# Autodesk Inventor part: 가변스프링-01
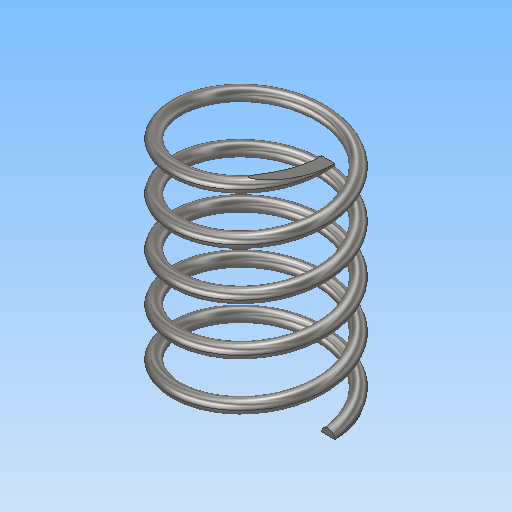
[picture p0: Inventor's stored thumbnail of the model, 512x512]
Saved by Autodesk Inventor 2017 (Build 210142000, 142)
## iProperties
Part Number: 가변스프링-01
Material: 강철, 연강
Document SubType Name: Modeling
Designer: MRC
Density: 7.85 g/cm^3
Appearance: 반연마
Mass: 8.42301 g
Surface Area: 21.7219 cm^2
Volume: 1.07299 cm^3
Author: MRC
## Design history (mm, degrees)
sketch "스케치1"
  geometry: L1 (0, 0)-(11, 0); L2 (11, 0)-(11, 36.411); L3 (11, 36.411)-(0, 36.411); L4 (0, 36.411)-(0, 0); C1 r 1 at (11, 0)
  constraints: 8 end point, 2 parallel, 1 centre point, 1 coincident, 1 horizontal, 1 perpendicular
  dimensions: "d0" = 36.4112 distance of L3.end L1.start (derived); "d1" = 22 diameter of L2 L4; "d2" = 2 diameter of C1
feature "코일1" sketch "스케치1" pitch "d3" = 10; turns "d5" = 5; dims "d4" = 36.4112 (= d0), "d6" = 0, angle "d7" = 90 deg, angle "d8" = 90 deg, "d9" = 0, "d10" = 0
sketch "스케치2"
  geometry: L1 (36.411, 17.383)-(0, 17.383); L2 (0, 17.383)-(0, -17.383); L3 (0, -17.383)-(36.411, -17.383); L4 (36.411, -17.383)-(36.411, 17.383); 2 further points
  constraints: 8 end point, 2 parallel, 1 coincident, 1 horizontal, 1 midpoint, 1 perpendicular
  dimensions: "d11" = 36.4112 distance of L2.end L3.end (= d0); "d12" = 34.76604 distance of L3.end L1.start
extrude "돌출1" sketch "스케치2" stored distance "d13" = 47.75; taper "d14" = 0 deg
node "솔리드1"
